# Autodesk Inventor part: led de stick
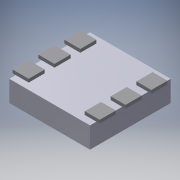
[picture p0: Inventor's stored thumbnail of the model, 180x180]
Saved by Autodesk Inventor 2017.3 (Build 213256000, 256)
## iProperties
Part Number: led de stick
Material: Générique
Document SubType Name: Modeling
Designer: ficho
Density: 1 g/cm^3
Appearance: Par défaut
Author: ficho
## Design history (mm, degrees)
sketch "Esquisse2"
  geometry: L1 (0, 0)-(5, 0); L2 (5, 0)-(5, 5); L3 (5, 5)-(0, 5); L4 (0, 5)-(0, 0)
  constraints: 8 end point, 2 parallel, 1 horizontal, 1 perpendicular
  dimensions: "d0" = 5 distance of L3.end L2.end; "d1" = 5 distance of L2.end L1.end
extrude "Extrusion1" new body sketch "Esquisse2" distance "d2" = 1.3; taper "d3" = 0 deg
sketch "Esquisse3"
  geometry: L1 (-0.2, 4.6)-(0.8, 4.6); L2 (0.8, 4.6)-(0.8, 3.6); L3 (0.8, 3.6)-(-0.2, 3.6); L4 (-0.2, 3.6)-(-0.2, 4.6); L5 (-0.2, 3)-(0.8, 3); L6 (0.8, 3)-(0.8, 2); L7 (0.8, 2)-(-0.2, 2); L8 (-0.2, 2)-(-0.2, 3); L9 (-0.2, 1.4)-(0.8, 1.4); L10 (0.8, 1.4)-(0.8, 0.4); L11 (0.8, 0.4)-(-0.2, 0.4); L12 (-0.2, 0.4)-(-0.2, 1.4); L13 (4.279, 4.6)-(5.2, 4.6); L14 (5.2, 4.6)-(5.2, 3.6); L15 (5.2, 3.6)-(4.279, 3.6); L16 (4.279, 3.6)-(4.279, 4.6); L17 (4.279, 3)-(5.2, 3); L18 (5.2, 3)-(5.2, 2); L19 (5.2, 2)-(4.279, 2); L20 (4.279, 2)-(4.279, 3); L21 (4.279, 1.4)-(5.2, 1.4); L22 (5.2, 1.4)-(5.2, 0.4); L23 (5.2, 0.4)-(4.279, 0.4); L24 (4.279, 0.4)-(4.279, 1.4); L25 (0, 5)-(0, 0) reference; L26 (0, 0)-(5, 0) reference
  constraints: 48 end point, 14 point on line, 12 parallel, 6 horizontal, 6 perpendicular
  dimensions: "d4" = 1 distance between parallel lines of L3 L1; "d5" = 1 distance between parallel lines of L7 L5 (= d4); "d6" = 1 distance between parallel lines of L11 L9 (= d5); "d7" = 4.2 distance between parallel lines of L1 L11; "d8" = 0.6 distance between parallel lines of L5 L3; "d9" = 5.4 distance between parallel lines of L22 L12; "d10" = 0.2 distance between parallel lines of L25 L4; "d11" = 1 distance between parallel lines of L2 L4; "d18" = 0.4 distance between parallel lines of L23 L26
extrude "Extrusion2" join sketch "Esquisse3" distance "d12" = 0.2; taper "d13" = 0 deg
sketch "Esquisse4"
  geometry: L1 (-5, 0)-(-5, 5) reference; L2 (-5, 5)-(0, 5) reference; C1 r 1.842 at (-2.5, 2.5); 1 further point
  constraints: 1 centre point
  dimensions: "d14" = 2.5 distance from line of C1.centre L1; "d15" = 2.5 distance from line of C1.centre L2 (= d14)
extrude "Extrusion3" join sketch "Esquisse4" distance "d16" = 0.1; taper "d17" = 0 deg
node "Solide1"
